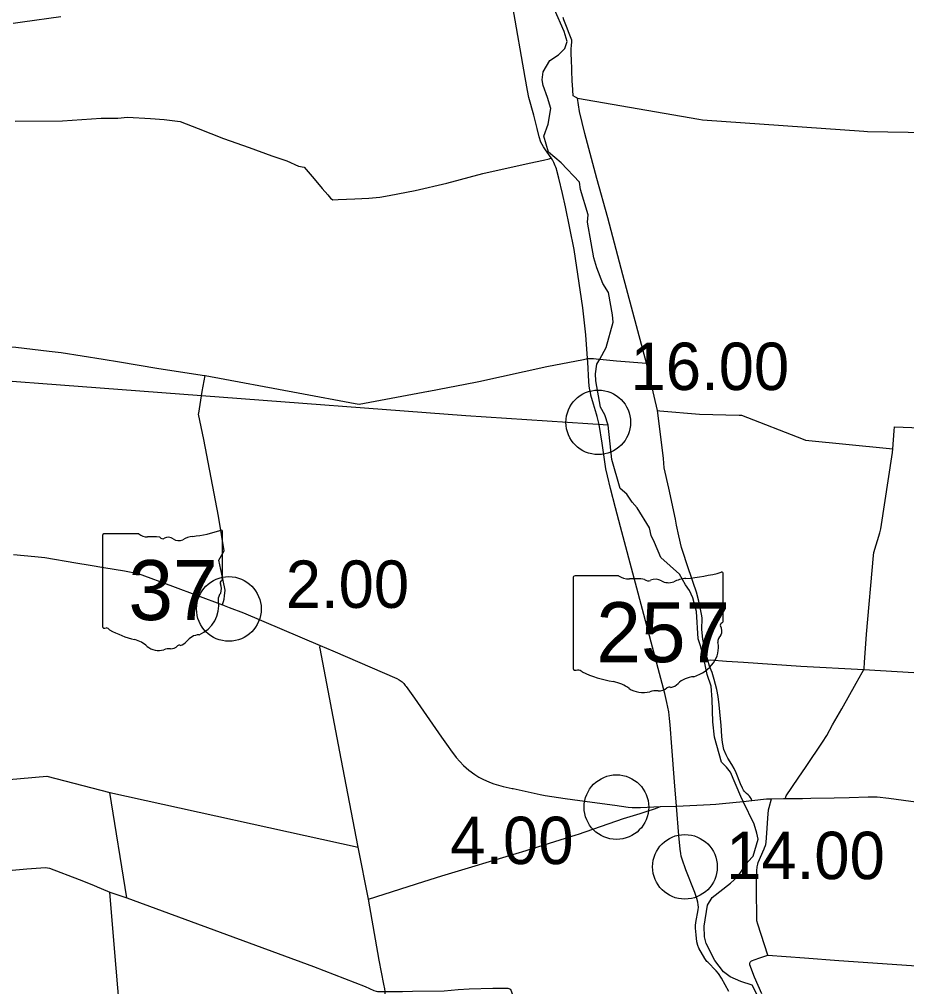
# Model space of a CAD drawing. Extents: x 1659811 to 1934326, y 644115 to 934867.
# Drawn here: x 1765018 to 1785602, y 842112 to 864569 of the extents above; entities that cross this region are included whole.
import ezdxf

# ---------------------------------------------------------------- set-up
doc = ezdxf.new("R2010")
doc.units = 0
for name, color, linetype in [('Default', 7, 'Continuous'), ('GM_X_County_Road', 7, 'Continuous'), ('GM_X_State_Route', 7, 'Continuous'), ('GM_X_State_Shield', 7, 'Continuous'), ('GM_X_Township', 7, 'Continuous'), ('GM_X_Township_Road', 7, 'Continuous')]:
    doc.layers.add(name, color=color, linetype=linetype)

msp = doc.modelspace()

# ---------------------------------------------------------------- linework, layer by layer
at = {"layer": 'Default'}
for centre in [(1778447, 855213), (1769878, 850881), (1778870, 846280), (1780458, 844894)]:
    msp.add_circle(centre, 750, dxfattribs=at)
at = {"layer": 'GM_X_County_Road'}
for points in [[(1779569, 856584), (1779019, 858639), (1778669, 859959), (1778417, 860876), (1778136, 861918), (1778010, 862427), (1777970, 862741)], [(1777970, 862741), (1780778, 862248), (1780868, 862232), (1784609, 861971), (1784696, 861964), (1786106, 861939), (1786241, 861929)], [(1761330, 857415), (1761757, 857293), (1762604, 857057), (1762687, 857045), (1762755, 857030), (1762889, 857019), (1763416, 856999), (1764783, 856969), (1764940, 856958), (1765711, 856869), (1765986, 856836), (1766962, 856678), (1767342, 856615), (1768207, 856468), (1769260, 856311), (1769327, 856301), (1771485, 855899), (1771485, 855899)], [(1774515, 855940), (1775597, 856145), (1775681, 856161), (1777256, 856513), (1778103, 856674), (1778201, 856693), (1778256, 856697), (1778340, 856696), (1778464, 856683)], [(1778464, 856683), (1778481, 856682), (1778870, 856644), (1779569, 856584)], [(1779821, 855489), (1779569, 856584)], [(1771485, 855899), (1772805, 855652), (1772899, 855634), (1774513, 855940), (1774515, 855940)], [(1779821, 855489), (1779879, 855478), (1780796, 855402), (1781715, 855381), (1781774, 855378), (1783200, 854819), (1783259, 854796), (1785203, 854604), (1785283, 854596)], [(1782794, 846480), (1782798, 846516), (1782808, 846543), (1783085, 846950), (1783272, 847226), (1783653, 847787), (1783748, 847942), (1783883, 848187), (1784102, 848564), (1784433, 849156), (1784568, 849404), (1784612, 849472), (1784619, 849495), (1784625, 849639), (1784668, 850295), (1784833, 852121), (1784839, 852194), (1784977, 852649), (1785005, 852740), (1785271, 854516), (1785283, 854596), (1785312, 855017), (1785318, 855106), (1786321, 855070)], [(1773032, 837243), (1772998, 837442), (1772959, 837683), (1772924, 837925), (1772923, 837966), (1772930, 838064), (1773454, 841640), (1773504, 841940), (1773503, 842000), (1773497, 842064), (1773475, 842168), (1773363, 842728), (1773117, 844144), (1772881, 845349), (1772483, 847403), (1771993, 849965), (1771991, 849978), (1771991, 849991), (1771992, 850005), (1771995, 850019), (1771999, 850032)], [(1782242, 841946), (1782072, 842331), (1781962, 842618), (1781962, 842650), (1781965, 842662), (1781975, 842683), (1782000, 842708), (1782174, 842776), (1782382, 842844), (1783229, 842784), (1784027, 842716), (1788298, 842429), (1791241, 842207), (1791633, 842186), (1792271, 842228), (1792567, 842237), (1792853, 842229), (1793017, 842224), (1793496, 842204), (1793598, 842199), (1793716, 842194), (1793856, 842196), (1793901, 842196), (1793954, 842199)]]:
    msp.add_lwpolyline(points, dxfattribs=at)
at = {"layer": 'GM_X_State_Route'}
for points in [[(1780260, 846299), (1780214, 846871), (1780156, 847683), (1780119, 848192), (1780103, 848341), (1780082, 848490), (1780037, 848711), (1779990, 848921), (1779866, 849386), (1779314, 851479), (1778967, 852787), (1778849, 853232), (1778732, 853677), (1778659, 853968), (1778625, 854134), (1778535, 854732), (1778466, 855163), (1778422, 855348), (1778404, 855403), (1778338, 855632), (1778279, 855845), (1778264, 855913), (1778254, 855963), (1778240, 856063), (1778232, 856164), (1778207, 856610), (1778201, 856693), (1778158, 857245), (1778089, 857871), (1777889, 859222), (1777685, 860217), (1777620, 860525), (1777532, 860880), (1777486, 861060), (1777476, 861098), (1777464, 861135), (1777451, 861171), (1777436, 861207), (1777419, 861242), (1777383, 861311), (1777355, 861355), (1777221, 861539), (1777176, 861609), (1777119, 861721), (1777075, 861838), (1777027, 862032), (1776950, 862347), (1776840, 862758), (1776807, 862917), (1776749, 863221), (1776467, 864856)], [(1764882, 852142), (1765375, 852101), (1765612, 852072), (1766327, 851954), (1766657, 851900), (1766981, 851843), (1767455, 851763), (1767775, 851700), (1768574, 851406), (1769730, 850976), (1769888, 850917), (1770221, 850789), (1771999, 850032), (1772292, 849906), (1773777, 849265), (1773831, 849237), (1773877, 849206), (1773898, 849188), (1773937, 849150), (1773955, 849129), (1773972, 849107), (1773988, 849084), (1774185, 848807), (1774812, 847908), (1774968, 847684)], [(1774968, 847684), (1775017, 847613), (1775152, 847432), (1775319, 847250), (1775446, 847139), (1775582, 847039), (1775677, 846979), (1775773, 846927), (1775925, 846858), (1776029, 846819), (1776243, 846761), (1776454, 846715), (1776476, 846710)], [(1776476, 846710), (1776545, 846695), (1777099, 846577), (1777213, 846553), (1777679, 846483), (1778305, 846395), (1778834, 846323), (1779138, 846279), (1779232, 846271), (1779274, 846270), (1779424, 846274), (1779888, 846291), (1780260, 846299)], [(1780260, 846299), (1780260, 846299), (1781047, 846338), (1781176, 846347), (1781331, 846363), (1781806, 846413), (1782009, 846435), (1782350, 846472), (1782467, 846475), (1782747, 846479)], [(1782747, 846479), (1782794, 846480), (1783183, 846484), (1783377, 846485), (1783923, 846492), (1784269, 846503), (1784713, 846520), (1784920, 846517), (1785189, 846487), (1785532, 846441), (1785928, 846388), (1786488, 846310), (1787292, 846217), (1788027, 846133), (1788780, 846042), (1789296, 845980), (1789805, 845926), (1790403, 845872), (1791058, 845819), (1791646, 845786), (1792283, 845741), (1792907, 845707), (1794165, 845645)], [(1781476, 841997), (1781310, 842306), (1781236, 842414), (1781182, 842481), (1780990, 842678), (1780970, 842699), (1780952, 842720), (1780919, 842766), (1780783, 843002), (1780756, 843068), (1780736, 843152), (1780719, 843314), (1780704, 843467), (1780704, 843535), (1780710, 843602), (1780766, 843894), (1780771, 843954), (1780769, 844015), (1780761, 844075), (1780737, 844162), (1780688, 844296), (1780481, 844827), (1780394, 845075), (1780375, 845141), (1780363, 845204), (1780347, 845305), (1780320, 845620), (1780260, 846299)]]:
    msp.add_lwpolyline(points, dxfattribs=at)
at = {"layer": 'GM_X_State_Shield'}
for p, q in [((1769731, 851569), (1769731, 852675)), ((1769731, 851569), (1769731, 852675)), ((1766947, 852586), (1766947, 850473)), ((1766947, 852586), (1766947, 850473)), ((1767790, 852623), (1766974, 852623)), ((1767790, 852623), (1766974, 852623)), ((1769731, 851570), (1769731, 851569)), ((1769731, 851570), (1769731, 851569)), ((1777866, 851609), (1777866, 849496)), ((1777866, 851609), (1777866, 849496)), ((1778920, 851646), (1777901, 851646)), ((1778920, 851646), (1777901, 851646)), ((1781347, 850593), (1781347, 851698)), ((1781347, 850593), (1781347, 851698)), ((1781346, 850593), (1781347, 850593)), ((1781346, 850593), (1781347, 850593))]:
    msp.add_line(p, q, dxfattribs=at)
for centre, radius, start, end in [((1768739, 855504), 2953, 275.8445, 288.9065), ((1768739, 855504), 2953, 275.8445, 288.9065), ((1769700, 852679), 31, 351.8621, 97.738), ((1769700, 852679), 31, 351.8621, 97.738), ((1766979, 852591), 32.3, 98.1301, 188.1301), ((1766979, 852591), 32.3, 98.1301, 188.1301), ((1767984, 852868), 313, 231.6195, 271.1119), ((1767984, 852868), 313, 231.6195, 271.1119), ((1768088, 851436), 1123, 80.4867, 94.9883), ((1768088, 851436), 1123, 80.4867, 94.9883), ((1768343, 852602), 90.3, 219.7921, 297.1024), ((1768343, 852602), 90.3, 219.7921, 297.1024), ((1768475, 852357), 188, 54.4667, 119.1411), ((1768475, 852357), 188, 54.4667, 119.1411), ((1768717, 852692), 226, 233.8562, 294.8282), ((1768717, 852692), 226, 233.8562, 294.8282), ((1769116, 851977), 594, 97.3462, 120.7689), ((1769116, 851977), 594, 97.3462, 120.7689), ((1769698, 851565), 33.2, 289.6038, 7.7341), ((1769698, 851565), 33.2, 289.6038, 7.7341), ((1769724, 851488), 48, 107.944, 210.337), ((1769724, 851488), 48, 107.944, 210.337), ((1769419, 851349), 288, 340.033, 23.6496), ((1769419, 851349), 288, 340.033, 23.6496), ((1769842, 851107), 210, 136.8065, 186.9296), ((1769842, 851107), 210, 136.8065, 186.9296), ((1768905, 850966), 739, 292.3089, 8.9858), ((1768905, 850966), 739, 292.3089, 8.9858), ((1766979, 850468), 32.5, 171.9584, 258.3066), ((1766979, 850468), 32.5, 171.9584, 258.3066), ((1766984, 850684), 248, 267.339, 280.6039), ((1766984, 850684), 248, 267.339, 280.6039), ((1767035, 850351), 89.5, 29.7484, 93.2717), ((1767035, 850351), 89.5, 29.7484, 93.2717), ((1768165, 852250), 2132, 240.4129, 257.1985), ((1768165, 852250), 2132, 240.4129, 257.1985), ((1769216, 849880), 404, 94.4031, 142.5768), ((1769216, 849880), 404, 94.4031, 142.5768), ((1767530, 849523), 667, 47.1842, 75.836), ((1767530, 849523), 667, 47.1842, 75.836), ((1768251, 850340), 423, 230.7004, 286.2918), ((1768251, 850340), 423, 230.7004, 286.2918), ((1768527, 850182), 226, 268.777, 315.5493), ((1768527, 850182), 226, 268.777, 315.5493), ((1768731, 849978), 63.5, 65.7517, 132.6484), ((1768731, 849978), 63.5, 65.7517, 132.6484), ((1768704, 850268), 239, 282.8732, 323.2771), ((1768704, 850268), 239, 282.8732, 323.2771), ((1768496, 849610), 348, 85.6951, 111.2099), ((1768496, 849610), 348, 85.6951, 111.2099)]:
    msp.add_arc(centre, radius, start, end, dxfattribs=at)
for centre, major_axis, start_param, end_param in [((1777906, 851614), (40.3, 0), 1.712693, 3.28349), ((1777906, 851614), (40.3, 0), 1.712693, 3.28349), ((1779162, 851891), (391, 0), 4.042523, 4.731795), ((1779162, 851891), (391, 0), 4.042523, 4.731795), ((1779292, 850459), (1404, 0), 1.404758, 1.657858), ((1779292, 850459), (1404, 0), 1.404758, 1.657858), ((1779611, 851625), (113, 0), 3.836095, 5.185415), ((1779611, 851625), (113, 0), 3.836095, 5.185415), ((1779777, 851381), (235, 0), 0.950623, 2.079405), ((1779777, 851381), (235, 0), 0.950623, 2.079405), ((1780578, 851000), (743, 0), 1.699011, 2.107814), ((1780578, 851000), (743, 0), 1.699011, 2.107814), ((1780107, 854527), (3691, 0), 4.814394, 5.042369), ((1780107, 854527), (3691, 0), 4.814394, 5.042369), ((1781308, 851703), (38.7, 0), 6.141152, 7.989035), ((1781308, 851703), (38.7, 0), 6.141152, 7.989035), ((1780079, 851716), (282, 0), 4.081561, 5.145723), ((1780079, 851716), (282, 0), 4.081561, 5.145723), ((1781338, 850511), (60, 0), 1.883978, 3.671073), ((1781338, 850511), (60, 0), 1.883978, 3.671073), ((1780956, 850372), (360, 0), 5.934695, 6.695948), ((1780956, 850372), (360, 0), 5.934695, 6.695948), ((1781305, 850588), (41.5, 0), 5.05454, 6.418171), ((1781305, 850588), (41.5, 0), 5.05454, 6.418171), ((1781485, 850130), (262, 0), 2.387724, 3.262537), ((1781485, 850130), (262, 0), 2.387724, 3.262537), ((1780314, 849989), (923, 0), 5.101752, 6.440018), ((1780314, 849989), (923, 0), 5.101752, 6.440018), ((1777906, 849491), (40.7, 0), 3.00124, 4.508301), ((1777906, 849491), (40.7, 0), 3.00124, 4.508301), ((1777913, 849708), (310, 0), 4.665946, 4.897461), ((1777913, 849708), (310, 0), 4.665946, 4.897461), ((1777976, 849374), (112, 0), 0.519207, 1.627899), ((1777976, 849374), (112, 0), 0.519207, 1.627899), ((1779389, 851273), (2665, 0), 4.195997, 4.488961), ((1779389, 851273), (2665, 0), 4.195997, 4.488961), ((1780703, 848903), (506, 0), 1.647645, 2.488434), ((1780703, 848903), (506, 0), 1.647645, 2.488434), ((1778595, 848547), (834, 0), 0.823519, 1.323587), ((1778595, 848547), (834, 0), 0.823519, 1.323587), ((1780062, 849291), (298, 0), 4.937069, 5.64225), ((1780062, 849291), (298, 0), 4.937069, 5.64225), ((1779497, 849364), (529, 0), 4.026481, 4.996735), ((1779497, 849364), (529, 0), 4.026481, 4.996735), ((1779802, 848633), (435, 0), 1.495662, 1.94098), ((1779802, 848633), (435, 0), 1.495662, 1.94098), ((1779841, 849205), (282, 0), 4.691044, 5.507374), ((1779841, 849205), (282, 0), 4.691044, 5.507374), ((1780096, 849001), (79.4, 0), 1.147584, 2.315152), ((1780096, 849001), (79.4, 0), 1.147584, 2.315152)]:
    msp.add_ellipse(centre, major_axis=major_axis, ratio=0.8, start_param=start_param, end_param=end_param, dxfattribs=at)
at = {"layer": 'GM_X_Township'}
for points in [[(1782290, 841614), (1782021, 842150), (1781758, 842232), (1781508, 842340), (1781351, 842454), (1781155, 842721), (1780952, 843117), (1780916, 843270), (1780907, 843520), (1780980, 844003), (1781094, 844181), (1781518, 844515), (1781682, 844666), (1781918, 845013), (1782045, 845142), (1782155, 845534), (1782125, 845674), (1782062, 845883), (1781806, 846413), (1781752, 846525), (1781519, 847094), (1781420, 847210), (1781308, 847324), (1781148, 847901), (1781109, 848257), (1781090, 848776), (1781068, 849092), (1780971, 849357), (1780904, 849691), (1780816, 850027), (1780762, 850186), (1780725, 850820), (1780641, 851138), (1780564, 851310), (1780471, 851440), (1780333, 851692), (1779900, 852077), (1779756, 852426), (1779678, 852587), (1779637, 852766), (1779349, 853231), (1779232, 853362), (1779109, 853545), (1778954, 853677), (1778765, 854353), (1778678, 855150), (1778601, 855389), (1778502, 855569), (1778390, 856177), (1778385, 856340), (1778415, 856566), (1778481, 856682), (1778631, 856948), (1778790, 857538), (1778777, 857706), (1778686, 858229), (1778551, 858440), (1778417, 858800), (1778344, 859030), (1778284, 859383), (1778195, 859863), (1778212, 860031), (1778036, 860617), (1778010, 860785), (1777585, 861235), (1777295, 861489), (1777189, 861855), (1777288, 862139), (1777344, 862501), (1777271, 862751), (1777172, 863030), (1777146, 863168), (1777170, 863351), (1777325, 863614), (1777527, 863741), (1777673, 863892), (1777723, 864054), (1777660, 864284), (1777430, 864796)], [(1778678, 855150), (1775377, 855361), (1769242, 855826), (1761265, 856432), (1759514, 856565)]]:
    msp.add_lwpolyline(points, dxfattribs=at)
at = {"layer": 'GM_X_Township_Road'}
for points in [[(1764876, 864478), (1765089, 864511), (1765980, 864631)], [(1777970, 862741), (1777923, 862765), (1777865, 862795), (1777848, 863058), (1777843, 863124), (1777826, 863652), (1777823, 863735), (1777822, 863788), (1777819, 863869), (1777829, 863974), (1777835, 864032), (1777835, 864085), (1777760, 864282), (1777729, 864364), (1777653, 864561), (1777633, 864611)], [(1764917, 862205), (1766017, 862209), (1766916, 862272), (1767304, 862272), (1767528, 862298), (1768057, 862265), (1768381, 862241), (1768751, 862199), (1769163, 862037), (1769751, 861801), (1770349, 861595), (1770876, 861403), (1771222, 861283), (1771494, 861163), (1771624, 861139), (1771860, 860864), (1772046, 860638), (1772174, 860498), (1772234, 860420), (1772290, 860376), (1772412, 860388), (1772798, 860402), (1773128, 860421), (1773381, 860443), (1773597, 860481), (1774197, 860598), (1774937, 860763), (1775772, 860991), (1776842, 861229), (1777174, 861301), (1777307, 861331), (1777355, 861355)], [(1769179, 855423), (1769242, 855826), (1769258, 855928), (1769327, 856301)], [(1769730, 850976), (1769768, 851110), (1769780, 851187), (1769790, 851318), (1769788, 851354), (1769715, 851685), (1769645, 852012), (1769767, 852228), (1769641, 853033), (1769298, 854816), (1769176, 855403), (1769177, 855414), (1769179, 855423)], [(1782009, 846435), (1781994, 846482), (1781973, 846515), (1781956, 846538), (1781929, 846565), (1781890, 846597), (1781839, 846644), (1781814, 846675), (1781792, 846718), (1781744, 846822), (1781649, 847077), (1781600, 847179), (1781548, 847266), (1781457, 847417), (1781415, 847493), (1781364, 847615), (1781331, 847781), (1781312, 847922), (1781300, 848183), (1781284, 848331), (1781251, 848655), (1781227, 848848), (1781196, 849012), (1781134, 849243), (1781087, 849407), (1781028, 849552), (1780989, 849690), (1780954, 849823), (1780912, 849990), (1780877, 850183), (1780851, 850403), (1780857, 850663), (1780848, 850718), (1780780, 851064), (1780725, 851272), (1780652, 851494), (1780597, 851656), (1780552, 851786), (1780381, 852308), (1780317, 852579), (1780262, 852823), (1780236, 852965), (1780083, 853686), (1779980, 854155), (1779958, 854372), (1779890, 854936), (1779821, 855489)], [(1780989, 849690), (1781043, 849696), (1781425, 849669), (1781815, 849644), (1783144, 849553), (1784612, 849472)], [(1784612, 849472), (1786799, 849340), (1790129, 849115), (1790221, 849109), (1791065, 849081), (1791820, 849028), (1792506, 848978), (1792740, 848959)], [(1762856, 846750), (1765656, 846999), (1767114, 846620), (1772881, 845349)], [(1767508, 844174), (1767114, 846620)], [(1782382, 842844), (1782151, 843564), (1782126, 843641), (1782122, 844417), (1782128, 844831), (1782131, 844863), (1782135, 844894), (1782148, 844956), (1782159, 844992), (1782295, 845310), (1782307, 845335), (1782325, 845387), (1782332, 845413), (1782342, 845467), (1782359, 845678), (1782380, 846027), (1782397, 846217), (1782411, 846275), (1782467, 846475)], [(1773117, 844144), (1774403, 844551), (1774819, 844683), (1776619, 845225), (1776675, 845242), (1777936, 845634), (1777990, 845650), (1779036, 846015), (1779423, 846131), (1779582, 846185), (1779752, 846241), (1779888, 846291)], [(1762874, 844646), (1763140, 844664), (1765191, 844845), (1765624, 844879), (1765716, 844865), (1766402, 844601), (1766735, 844466), (1766824, 844428)], [(1766824, 844428), (1767061, 844328), (1767115, 844306), (1767508, 844174), (1771842, 842582), (1773043, 842113), (1773241, 842025), (1773292, 842008), (1773324, 842000), (1773359, 841996), (1773503, 842000), (1773908, 842003), (1774142, 842004), (1774870, 842013), (1775194, 842043), (1775452, 842064), (1776003, 842077), (1776186, 842079), (1776350, 842079), (1776414, 842051), (1776523, 841761), (1776957, 840456), (1777434, 839004)], [(1768038, 833441), (1768025, 833543), (1768017, 833568), (1767945, 833784), (1767930, 833832), (1767921, 833869), (1767913, 833906), (1767904, 833971), (1767729, 835522), (1767660, 836277), (1767716, 836738), (1767746, 837037), (1767769, 837171), (1767731, 837552), (1767649, 838423), (1767510, 839758), (1767352, 841532), (1767215, 843091), (1767115, 844306)]]:
    msp.add_lwpolyline(points, dxfattribs=at)

# ---------------------------------------------------------------- texts
at = {"layer": 'Default'}
for s, p in [('16.00', (1779197, 855963)), ('2.00', (1771198, 850906)), ('4.00', (1775012, 844958)), ('14.00', (1781415, 844608))]:
    msp.add_text(s, height=1100, dxfattribs=at).set_placement(p)
at = {"layer": 'GM_X_State_Shield'}
for s, p in [('37', (1767548, 850622)), ('37', (1767548, 850622)), ('257', (1778402, 849645)), ('257', (1778402, 849645))]:
    msp.add_text(s, height=1392.2, dxfattribs=at).set_placement(p)

doc.saveas('drawing.dxf')
